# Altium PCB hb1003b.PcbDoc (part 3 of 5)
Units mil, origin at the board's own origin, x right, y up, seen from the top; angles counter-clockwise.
Board outline 2757 x 3548 mil, 2 copper layers (Top Layer, Bottom Layer); 120 components, 120 nets, 466 pads, 329 vias.
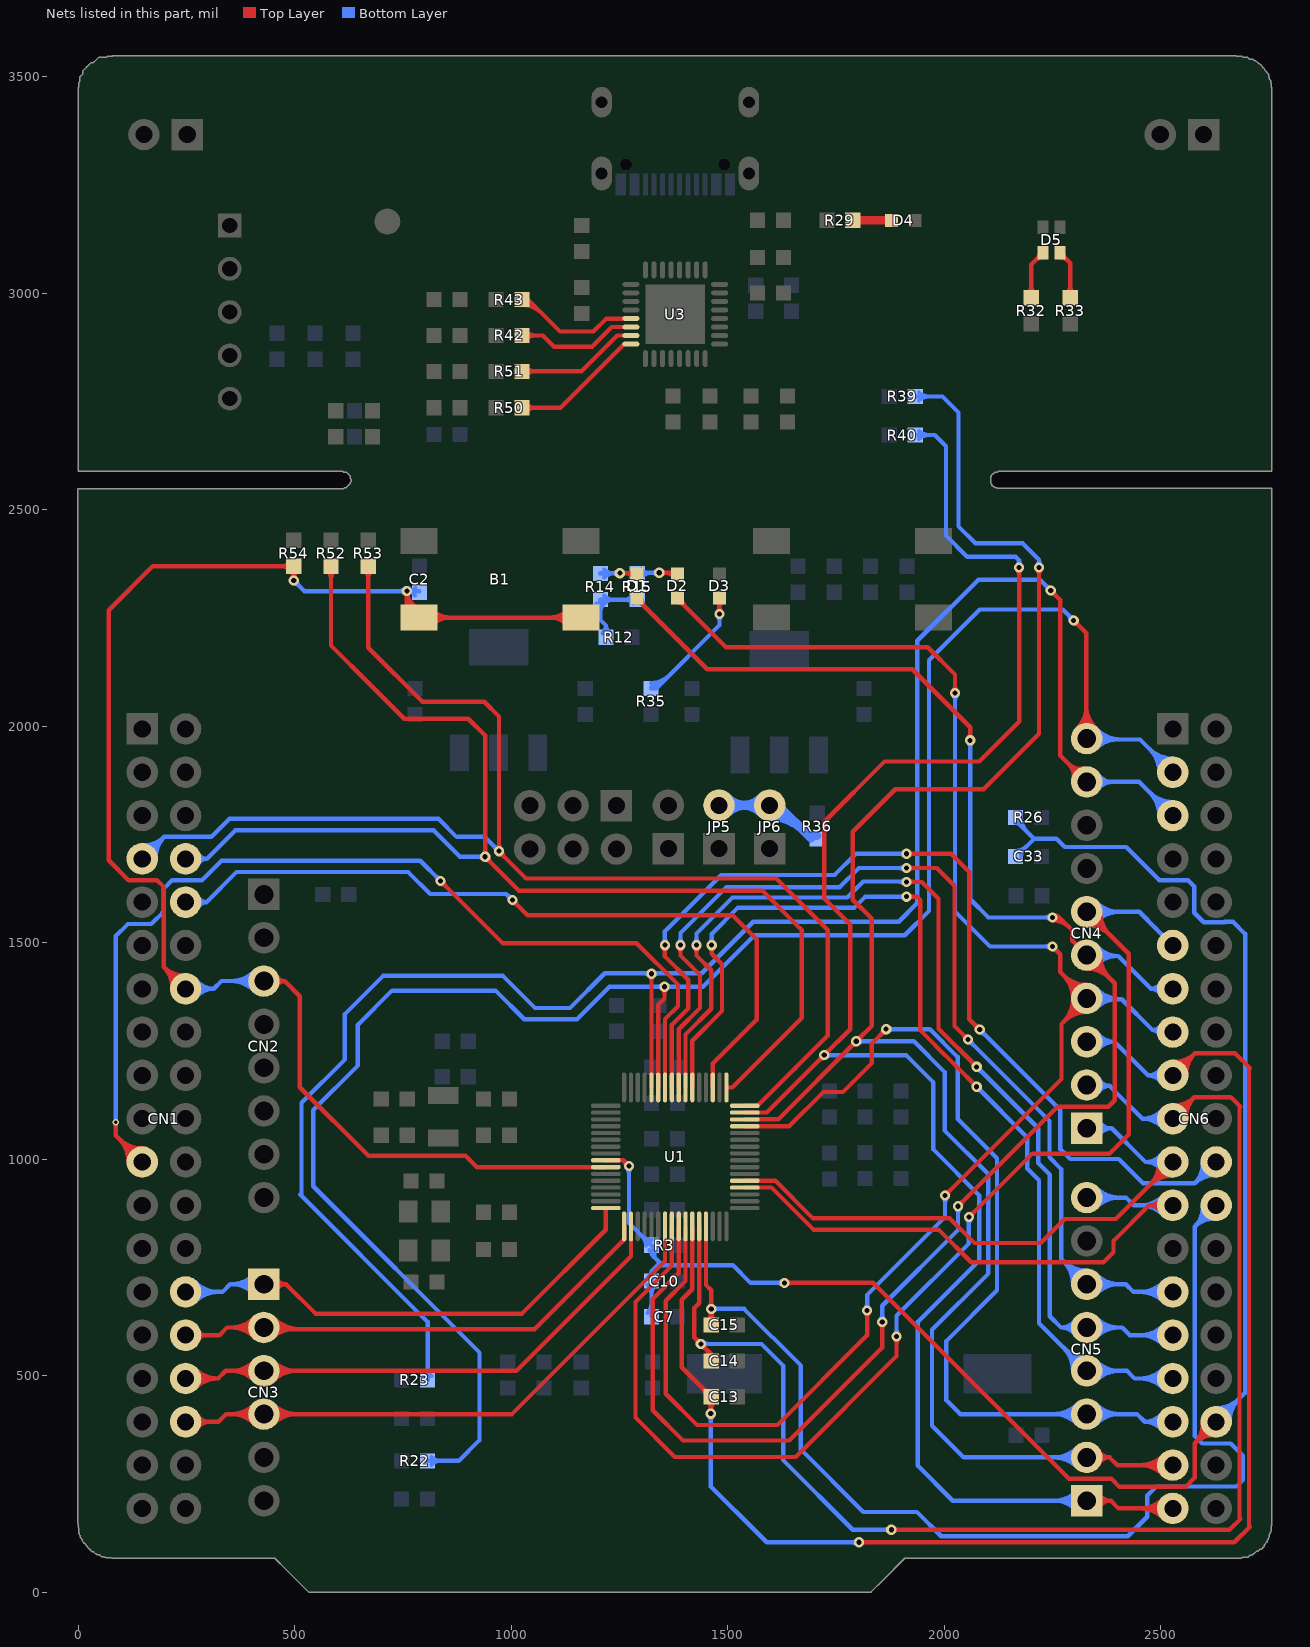
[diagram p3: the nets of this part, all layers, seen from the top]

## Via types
v1: diameter 23.62, hole 11.81, Top Layer to Bottom Layer, tented both sides, 290 vias
v2: diameter 39.37, hole 23.62, Top Layer to Bottom Layer, tented both sides, 29 vias
v3: diameter 15, hole 8, Top Layer to Bottom Layer, tented both sides, 10 vias

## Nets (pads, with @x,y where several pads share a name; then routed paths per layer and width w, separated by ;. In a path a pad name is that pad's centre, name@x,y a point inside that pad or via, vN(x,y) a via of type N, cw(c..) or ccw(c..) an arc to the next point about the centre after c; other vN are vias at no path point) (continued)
NetD1_1: D1.1 R14.1 | length 222.4
  Top Layer w10: v1(1251,2353) D1.1@1289,2353 ; v1@1255.82,2348.18 cw(c1267.44,2336.56) 1267.44,2353 cw(c1267.44,2369.44) v1@1255.82,2357.82 ; v1@1262.03,2353 cw(c1262.03,2322.03) D1.1@1283.93,2343.93 ; 1271.69,2353 ccw(c1271.69,2370.31) D1.1@1283.93,2358.07 ; D1.1@1291,2351 D1.1@1291,2353
  Bottom Layer w10: R14.1@1206,2352 1207,2353 v1(1251,2353) ; R14.1@1214.84,2343.16 cw(c1238.59,2319.41) 1238.59,2353 ; R14.1@1214.84,2360.84 ccw(c1233.77,2379.77) 1233.77,2353 ; v1@1246.18,2348.18 ccw(c1234.56,2336.56) 1234.56,2353 ccw(c1234.56,2369.44) v1@1246.18,2357.82
NetD2_1: D2.1 R15.1 | length 228.8
  Top Layer w10: v1(1342,2354) D2.1@1381,2354 ; v1@1346.82,2349.18 cw(c1358.44,2337.56) 1358.44,2354 cw(c1358.44,2370.44) v1@1346.82,2358.82 ; v1@1352.62,2354 cw(c1352.62,2319.62) D2.1@1376.93,2343.93 ; 1367.1,2354 ccw(c1367.1,2367.9) D2.1@1376.93,2358.07 ; D2.1@1384,2350 D2.1@1384,2351
  Bottom Layer w10: R15.1@1291,2352 1293,2354 v1(1342,2354) ; R15.1@1299.84,2343.16 cw(c1326.01,2317) 1326.01,2354 ; R15.1@1299.84,2360.84 ccw(c1316.35,2377.35) 1316.35,2354 ; v1@1337.18,2349.18 ccw(c1325.56,2337.56) 1325.56,2354 ccw(c1325.56,2370.44) v1@1337.18,2358.82
NetD3_1: D3.1 R35.1 | length 445
  Top Layer w10: D3.1@1473.93,2288.93 cw(c1456.86,2271.86) 1481,2271.86 cw(c1505.14,2271.86) D3.1@1488.07,2288.93 ; v1@1476.18,2263.82 ccw(c1464.56,2275.44) 1481,2275.44 ccw(c1497.44,2275.44) v1@1485.82,2263.82 ; v1(1481,2259) D3.1@1481,2296
  Bottom Layer w10: R35.1@1323,2087 1335,2087 1481,2233 v1(1481,2259) ; R35.1@1323,2089.5 ccw(c1323,2124.51) 1347.75,2099.75 ; R35.1@1323,2099.5 ccw(c1323,2158.65) 1364.82,2116.82 ; v1@1476.18,2254.18 cw(c1464.56,2242.56) 1481,2242.56 cw(c1497.44,2242.56) v1@1485.82,2254.18
NetD4_1: D4.1 R29.2 | length 117.4
  Top Layer w20: R29.2@1789,3168 D4.1@1878,3168 ; R29.2@1794.3,3162.7 cw(c1807.11,3149.89) 1807.11,3168 cw(c1807.11,3186.11) R29.2@1794.3,3173.3
NetD5_1: D5.1 R32.2 | length 192.1
  Top Layer w10: R32.2@2192.16,2997.84 ccw(c2170.82,3019.18) 2201,3019.18 ccw(c2231.18,3019.18) R32.2@2209.84,2997.84 ; R32.2@2201,2989 2201,3066 D5.1@2228,3093 ; 2209.65,3074.65 cw(c2228,3056.3) D5.1@2228,3082.25 ; D5.1@2216.78,3081.78 ccw(c2208.51,3090.05) D5.1@2220.2,3090.05
NetD5_3: D5.3 R33.2 | length 190.8
  Top Layer w10: D5.3@2267.37,3082.25 cw(c2267.37,3056.3) 2285.72,3074.65 ; D5.3@2267.37,3093 2291,3069.37 R33.2@2291,2989 ; D5.3@2275.17,3090.05 ccw(c2286.86,3090.05) D5.3@2278.59,3081.78 ; R33.2@2282.16,2997.84 ccw(c2260.82,3019.18) 2291,3019.18 ccw(c2321.18,3019.18) R33.2@2299.84,2997.84
NetJP5_2: JP5.2 JP6.2 R36.1 | length 617.7
  Bottom Layer w20: JP5.2@1480,1817 JP6.2@1597,1817 JP6.2@1612,1817 ; JP5.2@1498.68,1798.32 cw(c1543.78,1753.22) 1543.78,1817 cw(c1543.78,1880.78) JP5.2@1498.68,1835.68 ; JP6.2@1578.32,1798.32 ccw(c1533.22,1753.22) 1533.22,1817 ccw(c1533.22,1880.78) JP6.2@1578.32,1835.68 ; JP6.2@1597,1790.58 cw(c1597,1678.52) 1676.24,1757.76 ; JP6.2@1597,1810.58 cw(c1597,1746.81) 1642.1,1791.9 ; JP6.2@1615,1819 R36.1@1693,1741 ; 1673.71,1760.29 ccw(c1707,1793.57) R36.1@1707,1746.5
NetR12_1: R12.1 R14.2 R15.2 | length 359.3
  Bottom Layer w10: R14.2@1197.16,2283.16 cw(c1175.82,2261.82) 1206,2261.82 cw(c1236.18,2261.82) 1214.84,2283.16 cw(c1236.18,2261.82) 1236.18,2292 cw(c1236.18,2322.18) R14.2@1214.84,2300.84 ; R12.1@1210.91,2214.53 ccw(c1196.09,2232) 1219,2232 ; R12.1@1219,2205 1219,2232 ; R12.1@1227.09,2214.53 cw(c1241.91,2232) 1219,2232 ; R15.2@1282.16,2283.16 ccw(c1260.82,2261.82) 1260.82,2292 ccw(c1260.82,2322.18) R15.2@1282.16,2300.84 ; R15.2@1291,2292 R14.2@1206,2292 1206,2245 1219,2232
NetR42_1: R42.1 U3.22 | length 330.6
  Top Layer w10: R42.1@1025,2902 1073,2902 1084.5,2890.5 1099,2876 1187,2876 1232.47,2921.47 U3.22@1278.61,2921.47 ; R42.1@1033.84,2893.16 cw(c1055.18,2871.82) 1055.18,2902 cw(c1055.18,2932.18) R42.1@1033.84,2910.84
NetR43_1: R43.1 U3.21 | length 378.3
  Top Layer w10: R43.1@1025,2972.5 cw(c1025,2908.52) 1070.24,2953.76 ; R43.1@1025,2982.5 cw(c1025,2942.66) 1053.17,2970.83 ; R43.1@1025,2985 1039,2985 1113,2911 1189.79,2911 1218.98,2940.19 1277.64,2940.19 U3.21@1278.61,2941.16
NetR50_1: R50.1 U3.24 | length 360
  Top Layer w10: R50.1@1025,2735 1114,2735 1261.1,2882.1 U3.24@1276.64,2882.1 ; R50.1@1033.84,2726.16 cw(c1055.18,2704.82) 1055.18,2735 cw(c1055.18,2765.18) R50.1@1033.84,2743.84
NetR51_1: R51.1 U3.23 | length 333.3
  Top Layer w10: R51.1@1025,2819 1162,2819 1244.79,2901.79 U3.23@1276.64,2901.79 ; R51.1@1033.84,2810.16 cw(c1055.18,2788.82) 1055.18,2819 cw(c1055.18,2849.18) R51.1@1033.84,2827.84
NRST: B1.3 B1.4 C2.1 CN1.14 CN2.3 R54.2 U1.10 | length 4790.3
  Top Layer w10: CN1.14@216.62,1394.83 ccw(c152.85,1398.07) 198,1443.23 ; CN1.14@226.61,1394.32 ccw(c183.14,1396.53) 213.92,1427.31 ccw(c244.7,1458.09) CN1.14@246.91,1414.62 ; CN1.14@246.4,1424.6 cw(c243.16,1488.38) 198,1443.23 ; CN1.14@248,1393.23 198,1443.23 ; CN2.3@429,1411 477,1411 ; CN2.3@457.79,1398.43 cw(c477,1390.04) 477,1411 ; CN2.3@457.79,1423.57 ccw(c477,1431.96) 477,1411 ; R54.2@489.16,2377.84 cw(c467.82,2399.18) 467.82,2369 cw(c467.82,2338.82) 489.16,2360.16 cw(c467.82,2338.82) 498,2338.82 cw(c528.18,2338.82) R54.2@506.84,2360.16 ; v1@493.18,2340.82 ccw(c481.56,2352.44) 498,2352.44 ccw(c514.45,2352.45) v1@502.82,2340.82 ; v1@498,2335 R54.2@498,2369 172,2369 70.58,2267.58 70.58,1690 116.58,1644 182,1644 198,1628 198,1443.23 ; v1@754.18,2307.18 cw(c742.56,2295.56) 759,2295.56 cw(c775.44,2295.56) v1@763.82,2307.18 ; 759,2281.45 ccw(c787.94,2281.45) B1.3@776.36,2254.93 ; 759,2296.72 ccw(c794.6,2296.72) B1.3@780.36,2264.09 ; B1.3@784.36,2273.26 cw(c801.27,2312) v1(759,2312) 759,2278.41 B1.3@786.99,2250.42 B1.4@1161.01,2250.42 ; B1.3@810.14,2239.87 cw(c835.61,2214.39) 835.61,2250.42 cw(c835.61,2286.44) B1.3@810.14,2260.97 ; B1.3@817.21,2232.8 cw(c859.76,2190.25) 859.76,2250.42 cw(c859.76,2310.58) B1.3@817.21,2268.04 ; B1.4@1130.79,2232.8 ccw(c1088.24,2190.25) 1088.24,2250.42 ccw(c1088.24,2310.58) B1.4@1130.79,2268.04 ; B1.4@1137.86,2239.87 ccw(c1112.39,2214.39) 1112.39,2250.42 ccw(c1112.39,2286.44) B1.4@1137.86,2260.97 ; U1.10@1218.57,981.38 920.62,981.38 894,1008 670,1008 512,1166 512,1376 477,1411
  Bottom Layer w10: CN1.14@245.83,1399 CN1.14@248,1399 ; CN1.14@248,1393.23 313.23,1393.23 ; CN1.14@264.75,1379.88 cw(c292.46,1357.78) 292.46,1393.23 cw(c292.46,1428.68) CN1.14@264.75,1406.58 ; CN1.14@272.57,1373.64 cw(c313.22,1341.23) 313.22,1393.23 ; CN1.14@272.57,1412.81 ccw(c313.23,1445.23) 313.23,1393.23 ; CN2.3@406.78,1388.78 ccw(c353.15,1335.15) 353.15,1411 ccw(c353.15,1486.85) CN2.3@406.78,1433.22 ; CN2.3@413.86,1395.86 ccw(c377.29,1359.29) 377.29,1411 ccw(c377.29,1462.71) CN2.3@413.86,1426.14 ; CN2.3@429,1411 331,1411 313.23,1393.23 ; v1@498,2329.19 cw(c498,2312.75) 509.63,2324.37 cw(c521.25,2336) v1@504.81,2336 ; v1(498,2336) 522.56,2311.44 759,2311.44 v1@761,2311.44 ; 741.21,2311.44 ccw(c741.21,2329.79) v1@754.18,2316.82 ; 743.91,2311.44 cw(c743.91,2296.91) v1@754.18,2307.18 ; v1@763.71,2311.44 ccw(c763.71,2333.29) C2.1@779.16,2317.84 ; v1@763.82,2307.18 cw(c774.09,2296.91) C2.1@774.09,2311.44 ; v1@763.82,2316.82 ccw(c776.79,2329.79) C2.1@776.79,2311.44 ; C2.1@777.41,2302.36 ccw(c761,2292.08) v1@761,2311.44 ; C2.1@788,2311.44 v1@761,2311.44
PA0: C7.2 C10.2 C33.2 CN6.34 R3.1 R26.1 U1.9 | length 4788.2
  Top Layer w10: U1.9@1218.57,997.13 1258.87,997.13 v1(1272,984) ; v1@1265.19,984 ccw(c1248.75,984) 1260.37,995.63 ccw(c1272,1007.25) v1@1272,990.81 ; v1(1631,714) 1836,714 2288.42,261.58 2386.42,261.58 2405,243 2557,243 2578.58,264.58 2578.58,343.81 ; v1@1635.82,709.18 cw(c1647.44,697.56) 1647.44,714 cw(c1647.44,730.44) v1@1635.82,718.82 ; CN6.34@2596.64,391.36 cw(c2534.74,387.66) 2578.59,343.81 ; CN6.34@2606.62,391.95 cw(c2564.42,389.43) 2594.31,359.54 cw(c2624.21,329.65) CN6.34@2626.72,371.85 ; CN6.34@2625.61,395.61 CN6.34@2628,398 ; CN6.34@2626.13,361.87 ccw(c2622.44,299.96) 2578.58,343.81 ; CN6.34@2628,393.23 2578.58,343.81
  Bottom Layer w10: v1@1267.18,979.18 cw(c1255.56,967.56) 1272,967.56 cw(c1288.44,967.56) v1@1276.82,979.18 ; v1(1272,984) 1272,852 1323,801 R3.1@1324,801 1330.5,794.5 1330.5,773.5 ; 1300.95,823.05 ccw(c1324,846.09) R3.1@1324,813.5 ; 1303.37,820.63 cw(c1283.74,801) R3.1@1311.5,801 ; C7.2@1315.16,644.84 ccw(c1293.82,666.18) 1324,666.18 ccw(c1354.18,666.18) C7.2@1332.84,644.84 ; C10.2@1315.16,709.16 cw(c1293.82,687.82) 1324,687.82 cw(c1354.18,687.82) C10.2@1332.84,709.16 ; C10.2@1317.2,728.49 ccw(c1309.09,741) 1324,741 ; R3.1@1319.28,789.42 cw(c1312.49,772.74) 1330.5,772.74 ; C7.2@1324,636 C10.2@1324,718 1324,741 ; 1324,780 1330.5,773.5 ; C10.2@1330.8,728.49 cw(c1338.91,741) 1324,741 ; v1@1626.18,709.18 ccw(c1614.56,697.56) 1614.56,714 ccw(c1614.56,730.44) v1@1626.18,718.82 ; v1(1631,714) 1553,714 1512,755 1349,755 ; C33.2@2165,1694 C33.2@2166,1693 ; C33.2@2165,1711.5 ccw(c2165,1746.5) 2189.75,1721.75 ; R26.1@2165,1776.5 cw(c2165,1763.22) R26.1@2174.39,1772.61 ; R26.1@2165,1789 2165,1782 2205,1742 2205,1737 2178,1710 C33.2@2177,1710 ; R26.1@2167.5,1789 ccw(c2190.43,1789) R26.1@2174.22,1772.78 ; C33.2@2177.5,1699 cw(c2202.85,1699) 2184.92,1716.92 ; R26.1@2177.5,1789 ccw(c2224.58,1789) 2191.29,1755.71 ; 2206,1740 2244,1740 ; 2251,1740 2244,1740 ; 2396,1720.58 2376,1720.58 ; 2421.42,1719.58 2440,1701 ; CN6.34@2628,393.23 2695,460.23 2695,1520 2667,1548 2648.42,1548 2647.23,1546.81 2599.19,1546.81 2577.42,1568.58 2577.42,1629.58 2563,1644 2497,1644 2440,1701 ; CN6.34@2628,414.65 ccw(c2628,466.35) 2664.56,429.79 ccw(c2701.12,393.23) CN6.34@2649.42,393.23 ; CN6.34@2628,424.65 ccw(c2628,500.49) 2681.63,446.86 ccw(c2735.27,393.23) CN6.34@2659.42,393.23 ; 1324,741 1338,755 1349,755 ; 1330.5,773.5 1349,755 ; 2244,1740 2259,1740 2278.42,1720.58 2376,1720.58 ; 2376,1720.58 2420.42,1720.58 2440,1701
PA1: CN1.28 CN3.1 U1.16 | length 1594
  Top Layer w10: CN3.1@429,711 480,711 ; CN3.1@457.06,696.87 cw(c480,685.32) 480,711 ; CN3.1@457.06,725.13 ccw(c480,736.68) 480,711 ; U1.16@1218.57,886.89 1218.57,836.57 1025,643 548,643 480,711
  Bottom Layer w10: CN1.28@248,693.23 333.23,693.23 351,711 CN3.1@429,711 ; CN1.28@263.14,678.08 cw(c299.71,641.52) 299.71,693.23 cw(c299.71,744.93) CN1.28@263.14,708.37 ; CN1.28@270.22,671.01 cw(c323.85,617.38) 323.85,693.23 cw(c323.85,769.08) CN1.28@270.22,715.44 ; CN3.1@406.78,688.78 ccw(c353.15,635.15) 353.15,711 ccw(c353.15,786.85) CN3.1@406.78,733.22 ; CN3.1@413.86,695.86 ccw(c377.29,659.29) 377.29,711 ccw(c377.29,762.71) CN3.1@413.86,726.14
PA2: CN1.30 CN3.2 U1.17 | length 1611.6
  Top Layer w10: CN1.30@248,593.23 293,593.23 ; CN1.30@277.49,582.4 cw(c293,576.71) 293,593.23 ; CN1.30@277.49,604.05 ccw(c293,609.74) 293,593.23 ; CN3.2@406.78,588.78 ccw(c353.15,535.15) 353.15,611 ccw(c353.15,686.85) CN3.2@406.78,633.22 ; CN3.2@413.86,595.86 ccw(c377.29,559.29) 377.29,611 ccw(c377.29,662.71) CN3.2@413.86,626.14 ; CN3.2@437.07,619.07 ccw(c466.22,648.22) 466.22,607 ; CN3.2@444.14,595.86 cw(c471.05,568.95) 471.05,607 ; CN3.2@444.14,626.14 ccw(c490.36,672.36) 490.36,607 ; CN3.2@451.22,588.78 cw(c495.19,544.81) 495.19,607 ; CN3.2@451.22,633.22 ccw(c514.5,696.5) 514.5,607 ; U1.17@1260.89,844.57 1260.89,813.89 1054,607 433,607 CN3.2@429,611 344,611 326.23,593.23 293,593.23
PA3: CN1.32 CN3.3 U1.18 | length 1813.1
  Top Layer w10: CN1.32@248,493.23 323.23,493.23 341,511 CN3.3@429,511 1012,511 1276.64,775.64 U1.18@1276.64,844.57 ; CN1.32@263.23,478.17 cw(c299.28,442.55) 299.28,493.23 cw(c299.28,543.91) CN1.32@263.23,508.28 ; CN1.32@270.35,471.14 cw(c323.22,418.88) 323.22,493.23 cw(c323.22,567.57) CN1.32@270.35,515.31 ; CN3.3@406.78,488.78 ccw(c353.15,435.15) 353.15,511 ccw(c353.15,586.85) CN3.3@406.78,533.22 ; CN3.3@413.86,495.86 ccw(c377.29,459.29) 377.29,511 ccw(c377.29,562.71) CN3.3@413.86,526.14 ; CN3.3@444.14,495.86 cw(c480.71,459.29) 480.71,511 cw(c480.71,562.71) CN3.3@444.14,526.14 ; CN3.3@451.22,488.78 cw(c504.85,435.15) 504.85,511 cw(c504.85,586.85) CN3.3@451.22,533.22
PA4: CN1.34 CN3.4 U1.23 | length 1855.2
  Top Layer w10: CN1.34@248,393.23 303,393.23 ; CN1.34@266.45,382.35 cw(c285.49,371.12) 285.49,393.23 cw(c285.49,415.34) CN1.34@266.45,404.11 ; CN1.34@275.06,377.27 cw(c303,360.8) 303,393.23 ; CN1.34@275.06,409.19 ccw(c303,425.66) 303,393.23 ; CN3.4@406.78,388.78 ccw(c353.15,335.15) 353.15,411 ccw(c353.15,486.85) CN3.4@406.78,433.22 ; CN3.4@413.86,395.86 ccw(c377.29,359.29) 377.29,411 ccw(c377.29,462.71) CN3.4@413.86,426.14 ; CN3.4@444.14,395.86 cw(c480.71,359.29) 480.71,411 cw(c480.71,462.71) CN3.4@444.14,426.14 ; CN3.4@451.22,388.78 cw(c504.85,335.15) 504.85,411 cw(c504.85,486.85) CN3.4@451.22,433.22 ; U1.23@1355.38,844.57 1355.38,764.38 1002,411 CN3.4@429,411 342,411 324.23,393.23 303,393.23
PA5: CN4.6 CN6.11 U1.24 | length 3343.5
  Top Layer w10: U1.24@1371.13,844.57 1371.13,754.13 1287,670 1287,403 1378,312 1657.01,312 1890,544.99 v1(1890,590) ; v1@1885.18,585.18 cw(c1873.56,573.56) 1890,573.56 cw(c1906.44,573.56) v1@1894.82,585.18 ; v1(2057,866) 2203,1012 2381,1012 2426,1057 2426,1443 2426,1474 CN4.6@2331,1569 ; v1@2057,872.81 ccw(c2057,889.25) 2068.63,877.63 ccw(c2080.25,866) v1@2063.81,866 ; CN4.6@2329,1539.58 cw(c2329,1463.73) 2382.63,1517.37 cw(c2436.27,1571) CN4.6@2360.42,1571 ; CN4.6@2329,1549.58 cw(c2329,1497.88) 2365.56,1534.44 cw(c2402.12,1571) CN4.6@2350.42,1571
  Bottom Layer w10: v1@1885.18,594.82 ccw(c1873.56,606.44) 1890,606.44 ccw(c1906.44,606.44) v1@1894.82,594.82 ; v1(1890,590) 1890,638 2057,805 v1(2057,866) ; v1@2052.18,861.18 cw(c2040.56,849.56) 2057,849.56 cw(c2073.44,849.56) v1@2061.82,861.18 ; CN4.6@2329,1571 2450.23,1571 2490.61,1530.61 ; CN4.6@2344.14,1555.86 cw(c2380.71,1519.29) 2380.71,1571 cw(c2380.71,1622.71) CN4.6@2344.14,1586.14 ; CN4.6@2351.22,1548.78 cw(c2404.85,1495.15) 2404.85,1571 cw(c2404.85,1646.85) CN4.6@2351.22,1593.22 ; 2487.11,1534.11 2490.61,1530.61 ; CN6.11@2528,1493.23 2490.61,1530.61
PA6: CN4.5 CN6.13 D1.2 U1.25 | length 4979.2
  Top Layer w10: D1.2@1291,2286 cw(c1291,2269.1) D1.2@1302.95,2281.05 ; D1.2@1291,2296 1291,2293 1453,2131 1926,2131 2060,1997 v1(2060,1967) ; D1.2@1301,2296 ccw(c1332.39,2296) 1310.19,2273.81 ; U1.25@1386.87,844.57 1386.87,736.87 1327,677 1327,420 1397,350 1642,350 1857,565 v1(1857,624) ; v1@1852.18,619.18 cw(c1840.56,607.56) 1857,607.56 cw(c1873.44,607.56) v1@1861.82,619.18 ; v1(2032,891) 2262,1121 2379,1121 2394,1136 2394,1406 CN4.5@2331,1469 ; v1@2032,897.81 ccw(c2032,914.25) 2043.63,902.63 ccw(c2055.25,891) v1@2038.81,891 ; v1@2055.18,1971.82 ccw(c2043.56,1983.44) 2060,1983.44 ccw(c2076.44,1983.44) v1@2064.82,1971.82 ; v1@2248.29,1560.69 cw(c2255.57,1549.22) 2265.17,1558.83 ; v1@2250,1551.19 cw(c2250,1496.12) 2288.94,1535.06 ; v1(2250,1558) 2266,1558 ; v1@2250,1561.19 cw(c2250,1530.26) 2271.87,1552.13 ; v1@2253.65,1552.25 cw(c2262.42,1538.42) 2274,1550 ; v1@2254.91,1553.28 cw(c2266,1542.61) 2266,1558 ; v1@2254.91,1562.72 ccw(c2266,1573.39) 2266,1558 ; CN4.5@2328,1469 CN4.5@2331,1469 ; CN4.5@2329,1439.58 cw(c2329,1363.73) 2382.63,1417.37 cw(c2436.27,1471) CN4.5@2360.42,1471 ; CN4.5@2329,1449.58 cw(c2329,1397.88) 2365.56,1434.44 cw(c2402.12,1471) CN4.5@2350.42,1471 ; 2266,1558 2296,1528 2296,1504 CN4.5@2329,1471 CN4.5@2331,1469
  Bottom Layer w10: v1@1852.18,628.82 ccw(c1840.56,640.44) 1857,640.44 ccw(c1873.44,640.44) v1@1861.82,628.82 ; v1@1857,620 v1(1857,624) 1857,661 2032,836 v1(2032,891) ; v1@2027.18,886.18 cw(c2015.56,874.56) 2032,874.56 cw(c2048.44,874.56) v1@2036.82,886.18 ; v1@2055.18,1962.18 cw(c2043.56,1950.56) 2060,1950.56 cw(c2076.44,1950.56) v1@2064.82,1962.18 ; v1(2060,1967) 2060,1600 2102,1558 v1(2250,1558) ; v1@2245.18,1553.18 ccw(c2233.56,1541.56) 2233.56,1558 ccw(c2233.56,1574.44) v1@2245.18,1562.82 ; CN4.5@2328,1469 2402,1469 ; CN4.5@2344.14,1455.86 cw(c2375.88,1424.12) 2375.88,1469 ; CN4.5@2345.21,1485 ccw(c2380.15,1515.16) 2380.15,1469 ; CN4.5@2351.22,1448.78 cw(c2400.02,1399.98) 2400.02,1469 ; CN4.5@2352.78,1491.53 ccw(c2402,1534.02) 2402,1469 ; CN6.13@2499.75,1379.48 ccw(c2477.77,1368.79) 2477.77,1393.23 ; CN6.13@2499.75,1406.97 cw(c2477.77,1417.67) 2477.77,1393.23 ; CN6.13@2528,1393.23 2477.77,1393.23 ; 2402,1469 2477.77,1393.23
PA7: CN4.4 CN6.15 D2.2 U1.26 | length 4788.1
  Top Layer w10: D2.2@1384,2286 cw(c1384,2266.69) 1397.66,2280.34 ; D2.2@1384,2296 1384,2294 1496,2182 1962,2182 2025,2119 v1(2025,2076) ; D2.2@1394,2296 ccw(c1422.97,2296) 1402.49,2275.51 ; U1.26@1402.62,844.57 1402.62,718.46 1357,672.84 1357,458 1429,386 1615,386 1822,593 v1(1822,650) ; v1@1817.18,645.18 cw(c1805.56,633.56) 1822,633.56 cw(c1838.44,633.56) v1@1826.82,645.18 ; v1(2002,916) 2271,1185 2271,1312 CN4.4@2328,1369 ; v1@2002,922.81 ccw(c2002,939.25) 2013.63,927.63 ccw(c2025.25,916) v1@2008.81,916 ; v1@2020.18,2080.82 ccw(c2008.56,2092.44) 2025,2092.44 ccw(c2041.44,2092.44) v1@2029.82,2080.82 ; v1@2250,1484.19 cw(c2250,1467.75) 2261.63,1479.37 cw(c2273.25,1491) v1@2256.81,1491 ; v1(2250,1491) 2268,1473 2268,1432 CN4.4@2329,1371 ; 2274.66,1315.66 ccw(c2219.32,1371) 2297.58,1371 ccw(c2221.73,1371) 2275.37,1424.63 ccw(c2329,1478.27) CN4.4@2329,1402.42 ; 2277.07,1318.07 cw(c2329,1266.15) CN4.4@2329,1339.58 ; 2291.73,1332.73 ccw(c2253.46,1371) 2307.58,1371 ccw(c2255.88,1371) 2292.44,1407.56 ccw(c2329,1444.12) CN4.4@2329,1392.42 ; 2294.15,1335.15 cw(c2329,1300.29) CN4.4@2329,1349.58
  Bottom Layer w10: v1@1817.18,654.82 ccw(c1805.56,666.44) 1822,666.44 ccw(c1838.44,666.44) v1@1826.82,654.82 ; v1(1822,650) 1822,686 2002,866 v1(2002,916) ; v1@1997.18,911.18 cw(c1985.56,899.56) 2002,899.56 cw(c2018.44,899.56) v1@2006.82,911.18 ; v1@2020.18,2071.18 cw(c2008.56,2059.56) 2025,2059.56 cw(c2041.44,2059.56) v1@2029.82,2071.18 ; v1(2025,2076) 2025,1572 2106,1491 v1@2248,1491 ; v1@2245.18,1486.18 ccw(c2233.56,1474.56) 2233.56,1491 ccw(c2233.56,1507.44) v1@2245.18,1495.82 ; CN4.4@2328,1369 2410,1369 2481,1298 ; CN4.4@2328,1389 CN4.4@2336,1389 ; CN4.4@2344.14,1355.86 cw(c2375.88,1324.12) 2375.88,1369 ; CN4.4@2344.14,1386.14 ccw(c2385.53,1427.53) 2385.53,1369 ; CN4.4@2351.22,1348.78 cw(c2400.02,1299.98) 2400.02,1369 ; CN4.4@2351.22,1393.22 ccw(c2409.68,1451.68) 2409.68,1369 ; CN6.15@2497.63,1285.2 ccw(c2481,1280.8) 2481,1298 ; CN6.15@2501.04,1309.36 cw(c2481,1321.35) 2481,1298 ; CN6.15@2513,1298 2528,1298 2481,1298
PA8: CN5.8 CN6.23 U1.36 | length 1851.5
  Top Layer w10: U1.36@1539.43,934.13 1600.87,934.13 1698,837 1987,837 2062.42,761.58 2367.58,761.58 2391,785 2391,811 2473.23,893.23 ; CN6.23@2500.88,877.37 ccw(c2473.23,861.2) 2473.23,893.23 ; CN6.23@2500.88,909.09 cw(c2473.23,925.26) 2473.23,893.23 ; CN6.23@2509.51,882.42 ccw(c2490.66,871.39) 2490.66,893.23 ccw(c2490.66,915.06) CN6.23@2509.51,904.04 ; CN6.23@2526,898 CN6.23@2527,897 ; CN6.23@2528,893.23 2473.23,893.23
  Bottom Layer w10: CN5.8@2328,911 CN5.8@2329,911 2420,911 2433,898 2437.77,893.23 CN6.23@2528,893.23 ; CN5.8@2344.14,895.86 cw(c2380.71,859.29) 2380.71,911 cw(c2380.71,962.71) CN5.8@2344.14,926.14 ; CN5.8@2351.22,888.78 cw(c2404.85,835.15) 2404.85,911 cw(c2404.85,986.85) CN5.8@2351.22,933.22 ; CN6.23@2505.78,871.01 ccw(c2452.15,817.38) 2452.15,893.23 ccw(c2452.15,969.08) CN6.23@2505.78,915.44 ; CN6.23@2512.86,878.08 ccw(c2476.29,841.52) 2476.29,893.23 ccw(c2476.29,944.93) CN6.23@2512.86,908.37
PA9: CN4.1 CN6.21 U1.37 | length 1857.2
  Top Layer w10: U1.37@1539.43,949.88 1610.12,949.88 1697,863 2013,863 2070,806 2223,806 2278.58,861.58 2396.35,861.58 CN6.21@2528,993.23 ; CN4.1@2328,1088 2328,1089 CN4.1@2351,1089 ; CN6.21@2496.58,993.23 cw(c2420.73,993.23) 2474.37,939.6 cw(c2528,885.96) CN6.21@2528,961.81 ; CN6.21@2506.58,993.23 cw(c2454.88,993.23) 2491.44,956.67 cw(c2528,920.11) CN6.21@2528,971.81
  Bottom Layer w10: CN4.1@2328,1069 CN4.1@2329,1069 ; CN4.1@2329,1071 2387,1071 ; CN4.1@2346.94,1059.3 cw(c2368.54,1045.22) 2368.54,1071 cw(c2368.54,1096.78) CN4.1@2346.94,1082.7 ; CN4.1@2355.32,1053.84 cw(c2387,1033.18) 2387,1071 ; CN4.1@2355.32,1088.16 ccw(c2387,1108.82) 2387,1071 ; CN6.21@2502.96,974.25 ccw(c2464.78,945.32) 2464.78,993.23 ccw(c2464.78,1041.14) CN6.21@2502.96,1012.2 ; CN6.21@2510.93,980.29 ccw(c2484.9,960.57) 2484.9,993.23 ccw(c2484.9,1025.89) CN6.21@2510.93,1006.16 ; CN6.21@2528,993.23 2464.77,993.23 2460,998 2387,1071
PA10: CN5.3 CN6.33 U1.45 | length 2668.5
  Top Layer w10: U1.45@1539.43,1075.87 1641.87,1075.87 1721,1155 1766,1155 1833,1222 1833,1267 v1(1866,1300) ; v1@1859.19,1300 cw(c1842.75,1300) 1854.37,1288.37 cw(c1866,1276.75) v1@1866,1293.19
  Bottom Layer w10: v1(1866,1300) 1967,1300 2031,1236 2031,1093 2122,1002 2122,697 2005,580 2005,443 2037,411 CN5.3@2329,411 2445.23,411 2463,393.23 ; v1@1870.82,1295.18 cw(c1882.44,1283.56) 1882.44,1300 cw(c1882.44,1316.44) v1@1870.82,1304.82 ; CN5.3@2306.78,388.78 ccw(c2253.15,335.15) 2253.15,411 ccw(c2253.15,486.85) CN5.3@2306.78,433.22 ; CN5.3@2313.86,395.86 ccw(c2277.29,359.29) 2277.29,411 ccw(c2277.29,462.71) CN5.3@2313.86,426.14 ; CN5.3@2344.14,395.86 cw(c2380.71,359.29) 2380.71,411 cw(c2380.71,462.71) CN5.3@2344.14,426.14 ; CN5.3@2351.22,388.78 cw(c2404.85,335.15) 2404.85,411 cw(c2404.85,486.85) CN5.3@2351.22,433.22 ; CN6.33@2503.38,373.71 ccw(c2463,341.7) 2463,393.23 ; CN6.33@2503.38,412.74 cw(c2463,444.75) 2463,393.23 ; CN6.33@2511.22,379.92 ccw(c2483.69,358.1) 2483.69,393.23 ccw(c2483.69,428.35) CN6.33@2511.22,406.53 ; CN6.33@2528,393.23 2463,393.23
PA11: CN5.2 CN6.35 R39.2 U1.46 | length 4750.3
  Top Layer w10: U1.46@1539.43,1091.61 1616.61,1091.61 v1(1797,1272) 1833,1308 1833,1555 1789,1599 1789,1756 1887,1854 2091,1854 2219,1982 v1(2219,2366) ; v1@1790.19,1272 cw(c1773.75,1272) 1785.37,1260.37 cw(c1797,1248.75) v1@1797,1265.19 ; v1@1797,1278.81 ccw(c1797,1295.25) 1808.63,1283.63 ccw(c1820.25,1272) v1@1803.81,1272 ; v1@2214.18,2361.18 cw(c2202.56,2349.56) 2219,2349.56 cw(c2235.44,2349.56) v1@2223.82,2361.18 ; CN5.2@2329,311 2382,311 ; CN5.2@2356.56,295.92 cw(c2382,282.01) 2382,311 ; CN5.2@2356.56,326.08 ccw(c2382,339.99) 2382,311 ; CN6.35@2505.78,271.01 ccw(c2452.15,217.38) 2452.15,293.23 ccw(c2452.15,369.08) CN6.35@2505.78,315.44 ; CN6.35@2512.86,278.08 ccw(c2476.29,241.52) 2476.29,293.23 ccw(c2476.29,344.93) CN6.35@2512.86,308.37 ; CN6.35@2528,293.23 2399.77,293.23 2382,311
  Bottom Layer w10: v1(1797,1272) 1930,1272 2001,1201 2001,1066 2102,965 2102,736 1972,606 1972,384 2045,311 CN5.2@2329,311 ; v1@1801.82,1267.18 cw(c1813.44,1255.56) 1813.44,1272 cw(c1813.44,1288.44) v1@1801.82,1276.82 ; R39.2@1933,2761 1996,2761 2033,2724 2033,2461 2072,2422 2181,2422 2219,2384 v1(2219,2366) ; R39.2@1941.84,2752.16 cw(c1963.18,2730.82) 1963.18,2761 cw(c1963.18,2791.18) R39.2@1941.84,2769.84 ; v1@2214.18,2370.82 ccw(c2202.56,2382.44) 2219,2382.44 ccw(c2235.44,2382.44) v1@2223.82,2370.82 ; CN5.2@2306.78,288.78 ccw(c2253.15,235.15) 2253.15,311 ccw(c2253.15,386.85) CN5.2@2306.78,333.22 ; CN5.2@2313.86,295.86 ccw(c2277.29,259.29) 2277.29,311 ccw(c2277.29,362.71) CN5.2@2313.86,326.14
PA12: CN5.1 CN6.37 R40.2 U1.47 | length 4835.3
  Top Layer w10: U1.47@1539.43,1107.36 1590.36,1107.36 v1(1723,1240) 1783,1300 1783,1542 1723,1602 1723,1779 1862,1918 2081,1918 2173,2010 v1(2173,2366) v1@2173,2368 ; v1@1716.19,1240 cw(c1699.75,1240) 1711.37,1228.37 cw(c1723,1216.75) v1@1723,1233.19 ; v1@1723,1246.81 ccw(c1723,1263.25) 1734.63,1251.63 ccw(c1746.25,1240) v1@1729.81,1240 ; v1@2168.18,2361.18 cw(c2156.56,2349.56) 2173,2349.56 cw(c2189.44,2349.56) v1@2177.82,2361.18 ; CN5.1@2332,211 2385,211 ; CN5.1@2347.28,199.84 cw(c2367.17,187.69) 2367.17,211 cw(c2367.17,234.31) CN5.1@2347.28,222.16 ; CN5.1@2355.81,194.63 cw(c2385,176.8) 2385,211 ; CN5.1@2355.81,227.37 ccw(c2385,245.2) 2385,211 ; CN6.37@2505.78,171.01 ccw(c2452.15,117.38) 2452.15,193.23 ccw(c2452.15,269.08) CN6.37@2505.78,215.44 ; CN6.37@2512.86,178.08 ccw(c2476.29,141.52) 2476.29,193.23 ccw(c2476.29,244.93) CN6.37@2512.86,208.37 ; CN6.37@2528,193.23 2402.77,193.23 2385,211
  Bottom Layer w10: v1@1724.81,1238.19 v1(1723,1240) 1912,1240 1975,1177 1975,1151 ; v1@1727.82,1235.18 cw(c1739.44,1223.56) 1739.44,1240 cw(c1739.44,1256.44) v1@1727.82,1244.82 ; R40.2@1933,2672 1978,2672 2004,2646 2004,2440 2053,2391 2165,2391 2173,2383 v1(2173,2366) ; R40.2@1941.84,2663.16 cw(c1963.18,2641.82) 1963.18,2672 cw(c1963.18,2702.18) R40.2@1941.84,2680.84 ; 1975,1137 1975,1151 ; v1@2168.18,2370.82 ccw(c2156.56,2382.44) 2173,2382.44 ccw(c2189.44,2382.44) v1@2177.82,2370.82 ; CN5.1@2306.78,188.78 ccw(c2253.15,135.15) 2253.15,211 ccw(c2253.15,286.85) CN5.1@2306.78,233.22 ; CN5.1@2313.86,195.86 ccw(c2277.29,159.29) 2277.29,211 ccw(c2277.29,262.71) CN5.1@2313.86,226.14 ; CN5.1@2326,209 CN5.1@2328,211 ; CN5.1@2329,211 CN5.1@2328,211 ; 1975,1151 1975,1022 2081,916 2081,766 1939,624 1939,292 2020,211 CN5.1@2328,211
PA13: CN1.7 R53.2 U1.48 | length 3487
  Top Layer w10: R53.2@661.16,2360.16 cw(c639.82,2338.82) 670,2338.82 cw(c700.18,2338.82) R53.2@678.84,2360.16 ; R53.2@670,2369 670,2181 795,2056 938,2056 972,2022 v1(972,1711) 972,1710 1034,1648 1612,1648 1731,1529 1731,1478 ; v1@967.18,1715.82 ccw(c955.56,1727.44) 972,1727.44 ccw(c988.44,1727.44) v1@976.82,1715.82 ; v1@972,1704.19 cw(c972,1690.16) 981.92,1700.08 ; v1@978.81,1711 ccw(c997.67,1711) 984.33,1697.67 ; U1.48@1539.43,1123.11 1569.11,1123.11 1647,1201 ; 1657,1211 1647,1201 ; 1731,1412 1731,1478 ; 1647,1201 1731,1285 1731,1478
  Bottom Layer w10: CN1.7@148,1693.23 198.77,1744 ; CN1.7@148.85,1714.63 ccw(c150.63,1759.81) 182.61,1727.84 ccw(c214.58,1695.86) CN1.7@169.4,1694.07 ; CN1.7@149.24,1724.62 ccw(c151.86,1790.9) 198.77,1744 ; CN1.7@179.39,1694.47 cw(c245.67,1697.09) 198.77,1744 ; v1@965.19,1711 ccw(c948.75,1711) 960.37,1722.63 ccw(c972,1734.25) v1@972,1717.81 ; v1(972,1711) 939,1744 874,1744 832,1786 349.42,1786 307.42,1744 198.77,1744
PA14: CN1.8 R52.2 U1.49 | length 3122.9
  Top Layer w10: R52.2@575.16,2360.16 cw(c553.82,2338.82) 584,2338.82 cw(c614.18,2338.82) R52.2@592.84,2360.16 ; R52.2@584,2369 584,2186 673.5,2096.5 ; 647,2123 673.5,2096.5 ; v1@935.18,1702.82 ccw(c923.56,1714.44) 940,1714.44 ccw(c956.44,1714.44) v1@944.82,1702.82 ; v1@940,1691.19 cw(c940,1674.75) 951.63,1686.37 cw(c963.25,1698) v1@946.81,1698 ; v1@940,1699 940,1978 901,2017 753,2017 673.5,2096.5 ; v1@941,1697 1018.19,1619.81 1580.19,1619.81 1658,1542 ; U1.49@1497.11,1165.43 1510.43,1165.43 1671,1326 1671,1529 1658,1542 ; 1670,1530 1658,1542
  Bottom Layer w10: CN1.8@248,1693.23 297.23,1693.23 ; CN1.8@276.5,1680 cw(c297.23,1670.37) 297.23,1693.23 ; CN1.8@276.5,1706.46 ccw(c297.23,1716.08) 297.23,1693.23 ; v1@935.18,1693.18 ccw(c923.56,1681.56) 923.56,1698 ccw(c923.56,1714.44) v1@935.18,1702.82 ; v1(940,1698) 882,1698 821,1759 363,1759 297.23,1693.23
PA15: CN1.10 U1.51 | length 1900.7
  Top Layer w10: v1@999,1601 v1@999,1603 ; v1@1003,1591.19 cw(c1003,1574.75) 1014.63,1586.37 cw(c1026.25,1598) v1@1009.81,1598 ; v1(1003,1598) 1038,1563 1511,1563 1567,1507 1567,1322 1465.61,1220.61 U1.51@1465.61,1165.43
  Bottom Layer w8: CN1.10@228,1598 CN1.10@232.63,1598
  Bottom Layer w10: CN1.10@248,1593.23 296.23,1593.23 ; CN1.10@276.74,1580.53 cw(c296.23,1571.92) 296.23,1593.23 ; CN1.10@276.74,1605.92 ccw(c296.23,1614.53) 296.23,1593.23 ; v1@996.19,1598 ccw(c979.75,1598) 991.37,1609.63 ccw(c1003,1621.25) v1@1003,1604.81 ; v1@1001,1600 989,1612 813,1612 762,1663 366,1663 296.23,1593.23
PB0: C13.1 CN4.3 CN6.17 U1.27 | length 4134.8
  Top Layer w10: U1.27@1418.37,844.57 1418.37,699.37 1394,675 1394,519 C13.1@1462,451 1461,450 v1(1461,412) ; C13.1@1449.5,451 ccw(c1419.32,451) 1440.66,472.34 ccw(c1462,493.68) C13.1@1462,463.5 ; C13.1@1453.16,442.16 cw(c1434.23,423.23) v1@1461,423.23 ; v1@1456.18,416.82 ccw(c1444.56,428.44) 1461,428.44 ccw(c1477.44,428.44) v1@1465.82,416.82 ; v1@1461,418.41 cw(c1494.59,418.41) C13.1@1470.84,442.16 ; v1@1801,115 v1(1803,115) 2670,115 2706,151 ; v1@1807.82,110.18 cw(c1819.44,98.56) 1819.44,115 cw(c1819.44,131.44) v1@1807.82,119.82 ; CN6.17@2528,1193.23 2578.77,1244 ; CN6.17@2528,1198 CN6.17@2529.17,1198 ; CN6.17@2528.85,1214.63 ccw(c2530.63,1259.81) 2562.61,1227.84 ccw(c2594.58,1195.86) CN6.17@2549.4,1194.07 ; CN6.17@2529.24,1224.62 ccw(c2531.86,1290.9) 2578.77,1244 ; CN6.17@2559.39,1194.47 cw(c2625.67,1197.09) 2578.77,1244 ; 2704,151 2704,1210 ; 2706,1210 2672,1244 2578.77,1244
  Bottom Layer w10: v1@1456.18,407.18 cw(c1444.56,395.56) 1461,395.56 cw(c1477.44,395.56) v1@1465.82,407.18 ; v1(1461,412) 1461,244 1574,131 1589,116 1590,116 ; 1590,115 v1(1803,115) ; v1@1798.18,110.18 ccw(c1786.56,98.56) 1786.56,115 ccw(c1786.56,131.44) v1@1798.18,119.82 ; CN4.3@2329,1271 2393,1271 ; CN4.3@2345.94,1257.9 cw(c2372.63,1237.28) 2372.63,1271 cw(c2372.63,1304.72) CN4.3@2345.94,1284.1 ; CN4.3@2353.86,1251.79 cw(c2393,1221.53) 2393,1271 ; CN4.3@2353.86,1290.21 ccw(c2393,1320.47) 2393,1271 ; 2395,1269 2405.5,1258.5 ; 2470.78,1193.23 ccw(c2470.78,1229.64) CN6.17@2501.49,1210.09 ; CN6.17@2501.49,1176.36 ccw(c2470.77,1156.82) 2470.77,1193.23 ; CN6.17@2509.93,1181.73 ccw(c2488.99,1168.41) 2488.99,1193.23 ccw(c2488.99,1218.05) CN6.17@2509.93,1204.72 ; CN6.17@2525,1195 CN6.17@2528,1198 ; CN6.17@2528,1193.23 2470.77,1193.23 ; 2393,1271 2405.5,1258.5 ; 2405.5,1258.5 2466.5,1197.5 2470.77,1193.23
PB1: C14.1 CN4.2 CN6.19 U1.28 | length 3864.3
  Top Layer w10: v1@1431.19,573 ccw(c1414.75,573) 1426.37,584.63 ccw(c1438,596.25) v1@1438,579.81 ; U1.28@1434.12,844.57 1434.12,667.12 1423,656 1423,588 v1(1438,573) 1462,549 C14.1@1462,534 ; v1@1438,566.19 cw(c1438,549.75) 1449.63,561.37 cw(c1461.25,573) v1@1444.81,573 ; 1447.38,563.62 cw(c1418.11,534.36) C14.1@1459.5,534.02 ; v1(1878,144) 2659,144 2684,169 ; v1@1882.82,139.18 cw(c1894.44,127.56) 1894.44,144 cw(c1894.44,160.44) v1@1882.82,148.82 ; CN6.19@2528,1093.23 2577.77,1143 ; CN6.19@2529.16,1114.61 ccw(c2531.5,1157.59) 2561.93,1127.16 ccw(c2592.36,1096.72) CN6.19@2549.39,1094.39 ; CN6.19@2529.7,1124.6 ccw(c2533.13,1187.64) 2577.77,1143 ; CN6.19@2559.37,1094.93 cw(c2622.41,1098.36) 2577.77,1143 ; 2682,169 2682,1121 ; 2684,1121 2662,1143 2577.77,1143
  Bottom Layer w10: v1(1438,573) 1578,573 1628,523 1628,305 1789,144 v1(1878,144) ; v1@1442.82,568.18 cw(c1454.44,556.56) 1454.44,573 cw(c1454.44,589.44) v1@1442.82,577.82 ; v1@1873.18,139.18 ccw(c1861.56,127.56) 1861.56,144 ccw(c1861.56,160.44) v1@1873.18,148.82 ; CN4.2@2329,1171 2331,1169 2382,1169 ; CN4.2@2348.33,1180.23 ccw(c2366.14,1188.74) 2366.14,1169 ; CN4.2@2355.66,1154.38 cw(c2382,1137.97) 2382,1169 ; CN4.2@2357.35,1184.54 ccw(c2382,1196.32) 2382,1169 ; CN6.19@2504.58,1072.29 ccw(c2457.78,1030.45) 2457.78,1093.23 ccw(c2457.78,1156) CN6.19@2504.58,1114.17 ; CN6.19@2512.03,1078.95 ccw(c2480.13,1050.43) 2480.13,1093.23 ccw(c2480.13,1136.02) CN6.19@2512.03,1107.5 ; CN6.19@2528,1093.23 2457.77,1093.23 2382,1169
PB2: C15.1 CN6.24 U1.29 | length 2917.7
  Top Layer w10: 1449.87,709.13 1462,697 v1(1462,654) C15.1@1462,617 ; 1449.87,709.87 U1.29@1449.87,844.57 ; C15.1@1453.16,625.84 ccw(c1431.82,647.18) 1462,647.18 ccw(c1492.18,647.18) C15.1@1470.84,625.84 ; v1@1457.18,649.18 cw(c1445.56,637.56) 1462,637.56 cw(c1478.44,637.56) v1@1466.82,649.18 ; v1@1457.18,658.82 ccw(c1445.56,670.44) 1462,670.44 ccw(c1478.44,670.44) v1@1466.82,658.82
  Bottom Layer w10: v1(1462,654) 1538,654 1669,523 1669,329 1813,185 1937,185 1993,129 2424,129 2469,174 2469,223 2490,244 2507.34,244 2507.53,243.81 2526,243.81 2526.19,244 2675,244 2690,259 2690,315 2662,343 2596,343 2578.58,360.42 2578.58,843.81 ; v1@1466.82,649.18 cw(c1478.44,637.56) 1478.44,654 cw(c1478.44,670.44) v1@1466.82,658.82 ; CN6.24@2596.64,891.36 cw(c2534.74,887.66) 2578.59,843.81 ; CN6.24@2606.62,891.95 cw(c2564.42,889.43) 2594.31,859.54 cw(c2624.21,829.65) CN6.24@2626.72,871.85 ; CN6.24@2625.61,895.61 CN6.24@2628,898 ; CN6.24@2626.13,861.87 ccw(c2622.44,799.96) 2578.58,843.81 ; CN6.24@2628,893.23 2578.58,843.81
PB3: CN5.4 CN6.31 U1.54 | length 3392.1
  Top Layer w10: U1.54@1418.37,1165.43 1418.37,1273.37 1487,1342 1487,1450 1463,1474 v1(1463,1494) ; v1@1458.18,1489.18 cw(c1446.56,1477.56) 1463,1477.56 cw(c1479.44,1477.56) v1@1467.82,1489.18 ; v1@1462.5,1494.5 v1@1463,1495 ; v1(1913,1606) 1937,1606 1945,1598 1945,1297 2027,1215 ; v1@1917.82,1601.18 cw(c1929.44,1589.56) 1929.44,1606 cw(c1929.44,1622.44) v1@1917.82,1610.82 ; 1979,1263 2027,1215 ; v1@2068.19,1167 ccw(c2051.75,1167) 2063.37,1178.63 ccw(c2075,1190.25) v1@2075,1173.81 ; v1(2075,1167) 2027,1215
  Bottom Layer w10: v1@1458.18,1498.82 ccw(c1446.56,1510.44) 1463,1510.44 ccw(c1479.44,1510.44) v1@1467.82,1498.82 ; v1(1463,1494) 1463,1520 1523,1580 1792,1580 1818,1606 v1(1913,1606) ; v1@1908.18,1601.18 ccw(c1896.56,1589.56) 1896.56,1606 ccw(c1896.56,1622.44) v1@1908.18,1610.82 ; v1@2075,1160.19 cw(c2075,1143.75) 2086.63,1155.37 cw(c2098.25,1167) v1@2081.81,1167 ; v1(2075,1167) 2192,1050 2192,978 2219,951 2219,621 CN5.4@2329,511 ; CN5.4@2297.58,511 ccw(c2221.73,511) 2275.37,564.63 ccw(c2329,618.27) CN5.4@2329,542.42 ; CN5.4@2307.58,511 ccw(c2255.88,511) 2292.44,547.56 ccw(c2329,584.12) CN5.4@2329,532.42 ; CN5.4@2328,511 CN5.4@2329,511 ; CN5.4@2344.14,495.86 cw(c2380.71,459.29) 2380.71,511 cw(c2380.71,562.71) CN5.4@2344.14,526.14 ; CN5.4@2346.44,498.56 cw(c2370.58,481.34) 2370.58,511 cw(c2370.58,540.66) CN5.4@2346.44,523.44 ; CN5.4@2351.22,488.78 cw(c2404.85,435.15) 2404.85,511 cw(c2404.85,586.85) CN5.4@2351.22,533.22 ; CN5.4@2354.58,492.76 cw(c2390,467.49) 2390,511 ; CN5.4@2354.58,529.24 ccw(c2390,554.51) 2390,511 ; CN6.31@2505.78,471.01 ccw(c2452.15,417.38) 2452.15,493.23 ccw(c2452.15,569.08) CN6.31@2505.78,515.44 ; CN6.31@2512.86,478.08 ccw(c2476.29,441.52) 2476.29,493.23 ccw(c2476.29,544.93) CN6.31@2512.86,508.37 ; CN6.31@2528,493.23 2439.77,493.23 2435,498 2422,511 CN5.4@2329,511 ; CN5.4@2329,511 2390,511
PB4: CN5.5 CN6.29 U1.55 | length 3114.7
  Top Layer w10: U1.55@1402.62,1165.43 1402.62,1287.62 1462,1347 1462,1436 1428,1470 v1(1428,1494) ; v1@1423.18,1489.18 cw(c1411.56,1477.56) 1428,1477.56 cw(c1444.44,1477.56) v1@1432.82,1489.18 ; v1(1913,1640) 1948,1640 1987,1601 1987,1301 v1(2075,1213) ; v1@1917.82,1635.18 cw(c1929.44,1623.56) 1929.44,1640 cw(c1929.44,1656.44) v1@1917.82,1644.82 ; v1@2068.19,1213 ccw(c2051.75,1213) 2063.37,1224.63 ccw(c2075,1236.25) v1@2075,1219.81
  Bottom Layer w10: v1@1423.18,1498.82 ccw(c1411.56,1510.44) 1428,1510.44 ccw(c1444.44,1510.44) v1@1432.82,1498.82 ; v1(1428,1494) 1428,1521 1511,1604 1776,1604 1813,1641 1912,1641 v1(1913,1640) ; 1894.14,1641 cw(c1894.14,1621.14) v1@1908.18,1635.18 ; 1898.97,1641 ccw(c1898.97,1654.03) v1@1908.18,1644.82 ; v1@2075,1206.19 cw(c2075,1189.75) 2086.63,1201.37 cw(c2098.25,1213) v1@2081.81,1213 ; v1(2075,1213) 2217,1071 2217,991 2244,964 2244,637 2270,611 ; CN5.5@2302.93,593.46 ccw(c2270,571.31) 2270,611 ; CN5.5@2302.93,628.54 cw(c2270,650.69) 2270,611 ; CN5.5@2311.23,599.05 ccw(c2288.78,583.95) 2288.78,611 ccw(c2288.78,638.05) CN5.5@2311.23,622.95 ; CN5.5@2344.41,596.12 cw(c2379.44,562.3) 2379.44,611 cw(c2379.44,659.7) CN5.5@2344.41,625.88 ; CN5.5@2351.6,589.18 cw(c2403,539.57) 2403,611 ; CN5.5@2351.6,632.82 ccw(c2403,682.43) 2403,611 ; 2408,611 2403,611 ; 2427,595 2417.5,604.5 ; CN6.29@2505.78,571.01 ccw(c2452.15,517.38) 2452.15,593.23 ccw(c2452.15,669.08) CN6.29@2505.78,615.44 ; CN6.29@2507,598 2528,598 CN6.29@2525,595 ; CN6.29@2512.86,578.08 ccw(c2476.29,541.52) 2476.29,593.23 ccw(c2476.29,644.93) CN6.29@2512.86,608.37 ; CN6.29@2528,593.23 2428.77,593.23 2417.5,604.5 ; 2270,611 2328,611 CN5.5@2329,611 2403,611 ; 2403,611 2411,611 2417.5,604.5
PB5: CN5.6 CN6.27 U1.56 | length 3128.3
  Top Layer w10: v1@1386.18,1489.18 cw(c1374.56,1477.56) 1391,1477.56 cw(c1407.44,1477.56) v1@1395.82,1489.18 ; U1.56@1386.87,1165.43 1386.87,1299.87 1436,1349 1436,1425 1391,1470 v1(1391,1494) 1394,1491 v1@1394,1493 ; v1(1913,1672) 1983,1672 2024,1631 2024,1307 v1(2055,1276) ; v1@1917.82,1667.18 cw(c1929.44,1655.56) 1929.44,1672 cw(c1929.44,1688.44) v1@1917.82,1676.82 ; v1@2048.19,1276 ccw(c2031.75,1276) 2043.37,1287.63 ccw(c2055,1299.25) v1@2055,1282.81
  Bottom Layer w10: v1@1386.18,1498.82 ccw(c1374.56,1510.44) 1391,1510.44 ccw(c1407.44,1510.44) v1@1395.82,1498.82 ; v1(1391,1494) 1391,1522 1497,1628 1759,1628 1803,1672 v1(1913,1672) ; v1@1908.18,1667.18 ccw(c1896.56,1655.56) 1896.56,1672 ccw(c1896.56,1688.44) v1@1908.18,1676.82 ; v1@2055,1269.19 cw(c2055,1252.75) 2066.63,1264.37 cw(c2078.25,1276) v1@2061.81,1276 ; v1(2055,1276) 2243,1088 2243,1004 2270,977 2270,793 2270,770 CN5.6@2328.5,711.5 ; CN5.6@2297.58,711 ccw(c2221.73,711) 2275.37,764.63 ccw(c2329,818.27) CN5.6@2329,742.42 ; CN5.6@2307.58,711 ccw(c2255.88,711) 2292.44,747.56 ccw(c2329,784.12) CN5.6@2329,732.42 ; CN5.6@2328,711 CN5.6@2328.5,711.5 ; CN5.6@2332,715 CN5.6@2328.5,711.5 ; CN5.6@2344.14,695.86 cw(c2380.71,659.29) 2380.71,711 cw(c2380.71,762.71) CN5.6@2344.14,726.14 ; CN5.6@2351.22,688.78 cw(c2404.85,635.15) 2404.85,711 cw(c2404.85,786.85) CN5.6@2351.22,733.22 ; CN6.27@2505.78,671.01 ccw(c2452.15,617.38) 2452.15,693.23 ccw(c2452.15,769.08) CN6.27@2505.78,715.44 ; CN6.27@2512.86,678.08 ccw(c2476.29,641.52) 2476.29,693.23 ccw(c2476.29,744.93) CN6.27@2512.86,708.37 ; CN6.27@2528,693.23 2437.23,693.23 2419.46,711 CN5.6@2329,711 CN5.6@2328.5,711.5
PB6: CN6.22 U1.57 | length 2667.8
  Top Layer w10: v1@1350.18,1489.18 cw(c1338.56,1477.56) 1355,1477.56 cw(c1371.44,1477.56) v1@1359.82,1489.18 ; v1(1355,1494) 1355,1468 1409,1414 1409,1348 1371.13,1310.13 U1.57@1371.13,1165.43 ; v1(1913,1705) 2016,1705 2058,1663 2058,1323 v1(2082,1299) v1@2082.5,1298.5 ; v1@1917.82,1700.18 cw(c1929.44,1688.56) 1929.44,1705 cw(c1929.44,1721.44) v1@1917.82,1709.82 ; v1@2075.19,1299 ccw(c2058.75,1299) 2070.37,1310.63 ccw(c2082,1322.25) v1@2082,1305.81
  Bottom Layer w10: v1@1350.18,1498.82 ccw(c1338.56,1510.44) 1355,1510.44 ccw(c1371.44,1510.44) v1@1359.82,1498.82 ; v1(1355,1494) 1355,1526 1485,1656 1747,1656 1796,1705 v1(1913,1705) ; v1@1908.18,1700.18 ccw(c1896.56,1688.56) 1896.56,1705 ccw(c1896.56,1721.44) v1@1908.18,1709.82 ; v1@2082,1292.19 cw(c2082,1275.75) 2093.63,1287.37 cw(c2105.25,1299) v1@2088.81,1299 ; v1(2082,1299) 2268,1113 2268,1023 2291,1000 2403,1000 2459,944 2542,944 2578.77,944 ; CN6.22@2596.64,991.27 cw(c2535.34,987.43) 2578.77,944 ; CN6.22@2606.62,991.89 cw(c2564.84,989.28) 2594.44,959.67 cw(c2624.05,930.06) CN6.22@2626.66,971.85 ; CN6.22@2625.03,996.2 2626.83,998 CN6.22@2628,998 ; CN6.22@2626.04,961.87 ccw(c2622.2,900.57) 2578.77,944 ; CN6.22@2628,993.23 2578.77,944
PB7: CN1.21 U1.58 | length 2648.5
  Top Layer w10: v3(87,1085) 87,1054.23 CN1.21@148,993.23 ; CN1.21@116.58,993.23 ccw(c40.73,993.23) 94.37,1046.86 ccw(c148,1100.49) CN1.21@148,1024.65 ; CN1.21@126.58,993.23 ccw(c74.88,993.23) 111.44,1029.79 ccw(c148,1066.35) CN1.21@148,1014.65 ; v1@837,1635.19 cw(c837,1618.75) 848.63,1630.37 cw(c860.25,1642) v1@843.81,1642 ; v1(837,1642) 981,1498 1290,1498 1385.09,1402.91 1385.09,1352.91 1355.38,1323.2 U1.58@1355.38,1165.43
  Bottom Layer w10: v3(87,1085) 87,1272 ; 87,1242 87,1272 ; 127.77,1542.81 147,1542.81 ; 172.81,1546.81 194.5,1568.5 ; v1@830.19,1642 ccw(c813.75,1642) 825.37,1653.63 ccw(c837,1665.25) v1@837,1648.81 ; v1(837,1642) 790,1689 331,1689 286,1644 217,1644 198,1625 198,1572 194.5,1568.5 ; 87,1272 87,1515 114.81,1542.81 147,1542.81 ; 147,1542.81 168.81,1542.81 194.5,1568.5
PB8: CN4.10 CN6.3 R22.1 U1.59 | length 5376.4
  Top Layer w10: U1.59@1339.63,1165.43 1339.63,1356.63 ; 1340.38,1357.38 1354,1371 v1(1354,1398) ; v1@1349.18,1393.18 cw(c1337.56,1381.56) 1354,1381.56 cw(c1370.44,1381.56) v1@1358.82,1393.18 ; v1@2299,2237.19 cw(c2299,2220.75) 2310.63,2232.37 cw(c2322.25,2244) v1@2305.81,2244 ; v1(2299,2244) 2328,2215 2328,2162 ; CN4.10@2306.78,1993.22 ccw(c2255.57,2044.43) 2328,2044.43 ; CN4.10@2313.86,1986.14 ccw(c2279.71,2020.29) 2328,2020.29 ; CN4.10@2328,1968 2328,2162 ; 2328,2025.12 ccw(c2383.12,2025.12) CN4.10@2344.14,1986.14 ; 2328,2049.26 ccw(c2407.26,2049.26) CN4.10@2351.22,1993.22 ; 2328,2075 2328,2162
  Bottom Layer w10: R22.1@807,303 879,303 927,351 927,553 543,937 543,1113 646,1216 646,1310 725,1389 964,1389 1030,1323 1152,1323 1227,1398 v1(1354,1398) 1443,1398 1562,1517 1909,1517 1965,1573 1965,2152 2082,2269 2274,2269 v1(2299,2244) ; R22.1@815.84,294.16 cw(c837.18,272.82) 837.18,303 cw(c837.18,333.18) R22.1@815.84,311.84 ; v1@1349.18,1393.18 ccw(c1337.56,1381.56) 1337.56,1398 ccw(c1337.56,1414.44) v1@1349.18,1402.82 ; v1@1358.82,1393.18 cw(c1370.44,1381.56) 1370.44,1398 cw(c1370.44,1414.44) v1@1358.82,1402.82 ; v1@2292.19,2244 ccw(c2275.75,2244) 2287.37,2255.63 ccw(c2299,2267.25) v1@2299,2250.81 ; CN4.10@2329,1971 2331,1969 2452.23,1969 CN6.3@2528,1893.23 ; CN4.10@2344.14,1955.86 cw(c2375.88,1924.12) 2375.88,1969 ; CN4.10@2344.14,1986.14 ccw(c2385.53,2027.53) 2385.53,1969 ; CN4.10@2351.22,1948.78 cw(c2400.02,1899.98) 2400.02,1969 ; CN4.10@2351.22,1993.22 ccw(c2409.68,2051.68) 2409.68,1969 ; CN6.3@2496.58,1893.23 ccw(c2420.73,1893.23) 2474.37,1946.86 ccw(c2528,2000.49) CN6.3@2528,1924.65 ; CN6.3@2506.58,1893.23 ccw(c2454.88,1893.23) 2491.44,1929.79 ccw(c2528,1966.35) CN6.3@2528,1914.65
PB9: CN4.9 CN6.5 R23.1 U1.60 | length 5103.2
  Top Layer w10: v1@1319.18,1423.18 cw(c1307.84,1411.84) 1323.88,1411.84 ; U1.60@1323.88,1165.43 v1@1323.88,1428 ; 1323.88,1411.27 cw(c1340.73,1411.27) v1@1328.82,1423.18 ; v1@2246,2306.19 cw(c2246,2289.75) 2257.63,2301.37 cw(c2269.25,2313) v1@2252.81,2313 ; v1(2246,2313) 2268,2291 ; 2267.46,2290.46 2268,2289.91 2268,1932 2287.5,1912.5 ; CN4.9@2298.19,1877.17 ccw(c2259.85,1884.85) 2287.5,1912.5 ; CN4.9@2308,1875.21 ccw(c2281.86,1880.44) 2300.71,1899.29 ccw(c2319.56,1918.14) CN4.9@2324.79,1892 ; CN4.9@2322.83,1901.81 cw(c2315.15,1940.15) 2287.5,1912.5 ; CN4.9@2329,1871 2287.5,1912.5
  Bottom Layer w10: 513,918 795.5,635.5 ; 516,918 516,1130 616,1230 616,1335 704,1423 981,1423 1055,1349 1136,1349 1216,1429 1440,1429 1559,1548 1895,1548 1938,1591 1938,2197 2079,2338 2221,2338 v1(2246,2313) ; R23.1@798.16,498.84 ccw(c776.82,520.18) 807,520.18 ccw(c837.18,520.18) R23.1@815.84,498.84 ; 802,629 795.5,635.5 ; R23.1@807,490 807,624 795.5,635.5 ; 1305.14,1429 cw(c1305.14,1409.14) v1@1319.18,1423.18 ; 1309.97,1429 ccw(c1309.97,1442.03) v1@1319.18,1432.82 ; v1@1328.82,1423.18 cw(c1342.86,1409.14) 1342.86,1429 ; v1@1328.82,1432.82 ccw(c1338.03,1442.03) 1338.03,1429 ; v1@2239.19,2313 ccw(c2222.75,2313) 2234.37,2324.63 ccw(c2246,2336.25) v1@2246,2319.81 ; CN4.9@2328,1889 CN4.9@2335,1889 ; CN4.9@2329,1871 2388,1871 ; CN4.9@2346.77,1859.05 cw(c2369.22,1843.95) 2369.22,1871 cw(c2369.22,1898.05) CN4.9@2346.77,1882.95 ; CN4.9@2355.07,1853.46 cw(c2388,1831.31) 2388,1871 ; CN4.9@2355.07,1888.54 ccw(c2388,1910.69) 2388,1871 ; CN6.5@2496.58,1793.23 ccw(c2420.73,1793.23) 2474.37,1846.86 ccw(c2528,1900.49) CN6.5@2528,1824.65 ; CN6.5@2506.58,1793.23 ccw(c2454.88,1793.23) 2491.44,1829.79 ccw(c2528,1866.35) CN6.5@2528,1814.65 ; CN6.5@2528,1793.23 2450.23,1871 2388,1871
  other v1: 1324,1428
